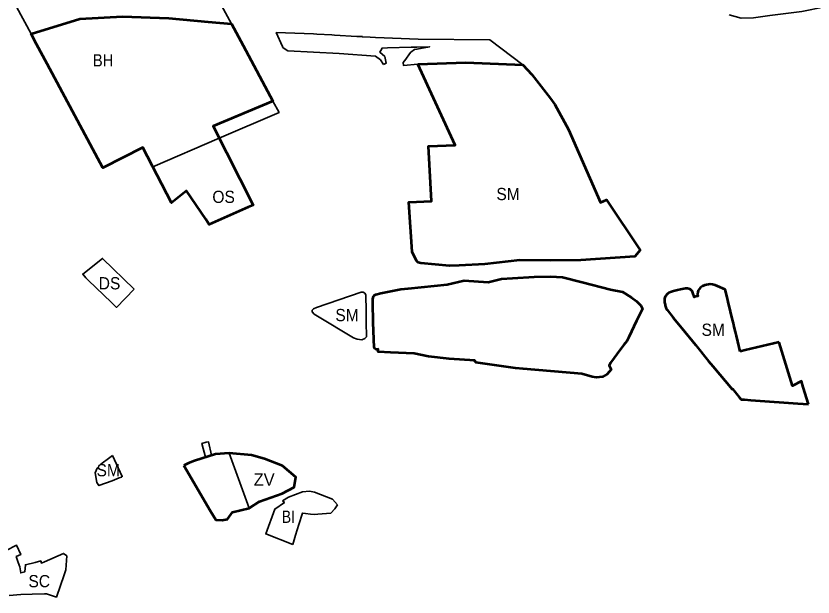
# Model space of a CAD drawing. Extents: x -650276 to -642489, y -1074311 to -1066658.
# Drawn here: x -647428 to -646647, y -1070424 to -1069855 of the extents above; entities that cross this region are included whole.
import ezdxf

# ---------------------------------------------------------------- set-up
doc = ezdxf.new("R2010")
doc.units = 0
doc.header["$LTSCALE"] = 4.8
for name, color, linetype, lineweight in [('1', 7, 'Continuous', 35), ('15', 7, 'Continuous', 35), ('17', 7, 'Continuous', 35), ('18', 7, 'Continuous', 35), ('2', 7, 'Continuous', 35), ('24', 7, 'Continuous', 35), ('25', 7, 'Continuous', 35), ('40', 7, 'Continuous', 35), ('60', 7, 'Continuous', 53), ('9', 7, 'Continuous', 35)]:
    doc.layers.add(name, color=color, linetype=linetype, lineweight=lineweight)
doc.layers.add('62', color=7, linetype='Continuous')
doc.layers.add('63', color=7, linetype='Continuous')

msp = doc.modelspace()

# ---------------------------------------------------------------- linework, layer by layer
at = {"layer": '1'}
msp.add_lwpolyline([(-647365.866, -1069857.774), (-647413.461, -1069872.442), (-647343.28, -1070003.81), (-647339.69, -1070001.95), (-647330.5, -1069997.19), (-647304.05, -1069983.79), (-647294.257, -1070002.745), (-647229.096, -1069974.658), (-647235, -1069963), (-647176.499, -1069938.333), (-647205.781, -1069883.796), (-647217.177, -1069862.57), (-647243.231, -1069860.34), (-647278.525, -1069857.002), (-647323.794, -1069855.468)], close=True, dxfattribs=at)
at = {"layer": '15'}
for points in [[(-647217.177, -1069862.57), (-647228.77, -1069840.98), (-647232.66, -1069841.07), (-647266.62, -1069837.86), (-647270.71, -1069837.61), (-647285.9, -1069836.66), (-647326.71, -1069835.46), (-647363.21, -1069836.64), (-647425.73, -1069844.31), (-647427.62, -1069845.94), (-647413.461, -1069872.442), (-647365.866, -1069857.774), (-647323.794, -1069855.468), (-647278.525, -1069857.002), (-647239.912, -1069860.654)], [(-647235, -1069963), (-647176.499, -1069938.333), (-647170.546, -1069949.42), (-647229.096, -1069974.658)], [(-647242.698, -1070287.238), (-647236.567, -1070285.154), (-647239.781, -1070272.031), (-647242.06, -1070272.35), (-647246.28, -1070273.733)]]:
    msp.add_lwpolyline(points, close=True, dxfattribs=at)
for points in [[(-646931.67, -1069902.89), (-646964.111, -1069878.315), (-647034.195, -1069877.629), (-647076, -1069875.85), (-647081.25, -1069875.56), (-647081.26, -1069875.76), (-647088.94, -1069875.34), (-647088.93, -1069875.14), (-647094.24, -1069874.85), (-647116.31, -1069873.65), (-647118.77, -1069873.51), (-647133.58, -1069872.73), (-647136.94, -1069872.55), (-647173.23, -1069871.09), (-647167.14, -1069884.85)], [(-647167.14, -1069884.85), (-647166.8, -1069885.63), (-647163.55, -1069887.98), (-647162.03, -1069888.89), (-647111.76, -1069891.77)], [(-647111.76, -1069891.77), (-647075.97, -1069894.33), (-647071, -1069897.87), (-647068.2, -1069902.28)], [(-647068.2, -1069902.28), (-647065.47, -1069901.09), (-647067.02, -1069894.68), (-647071.73, -1069890.39), (-647070.87, -1069888.71), (-647069.57, -1069886.35), (-647064.32, -1069886.23), (-647041.25, -1069885.62), (-647035.6, -1069885.43), (-647023.04, -1069885), (-647035.53, -1069887.44), (-647037.79, -1069887.88), (-647041.47, -1069890.42), (-647042.75, -1069892.14), (-647046.49, -1069897.19), (-647048.8, -1069900.51), (-647048.67, -1069903.32), (-647034.51, -1069902.21)], [(-647034.51, -1069902.21), (-647032.16, -1069902.13), (-646987.56, -1069900.52), (-646931.67, -1069902.89)]]:
    msp.add_lwpolyline(points, dxfattribs=at)
at = {"layer": '17'}
msp.add_lwpolyline([(-647434.85, -1070422.64), (-647423.38, -1070421.87), (-647412.51, -1070421.5), (-647400.41, -1070421.08), (-647398.21, -1070421.15), (-647388.6, -1070424.24), (-647381.11, -1070402.45), (-647379.3, -1070397.57), (-647378.49, -1070383.91), (-647381.65, -1070381.45), (-647400.22, -1070389.64), (-647403.27, -1070390.91), (-647404, -1070388.84), (-647409.36, -1070390.24), (-647419.08, -1070392.52), (-647419.68, -1070399.59), (-647423.58, -1070400.59), (-647424.54, -1070394.78), (-647425.99, -1070390.47), (-647427.96, -1070384.64), (-647423.57, -1070382.64), (-647427.8, -1070373.32), (-647437.76, -1070378.66)], dxfattribs=at)
at = {"layer": '18'}
for points in [[(-647032.16, -1069902.13), (-647034.51, -1069902.21), (-646998.06, -1069981.49), (-647024.05, -1069982.48), (-647021.27, -1070036.28), (-647043.25, -1070037.29), (-647040.12, -1070086.11), (-647036.03, -1070094.96), (-647034.17, -1070096.49), (-647031.73, -1070097.21), (-647003.49, -1070099.66), (-646993.92, -1070099.49), (-646968.89, -1070098.02), (-646934.63, -1070094.24), (-646904.97, -1070094.52), (-646874.9, -1070094.1), (-646859.29, -1070093.1), (-646821.89, -1070090.7), (-646817.15, -1070084.76), (-646816.9, -1070084.45), (-646837.65, -1070053.22), (-646849.79, -1070035.17), (-646855.62, -1070037.66), (-646886.85, -1069966.26), (-646900.26, -1069941.64), (-646904.72, -1069935.84), (-646922.79, -1069912.31), (-646931.67, -1069902.89), (-646987.56, -1069900.52)], [(-647097.63, -1070170.37), (-647093.89, -1070171.55), (-647089.47, -1070172.21), (-647086.62, -1070170.89), (-647084.98, -1070169.29), (-647085.17, -1070154.78), (-647085.24, -1070144.07), (-647085.62, -1070128.24), (-647086.49, -1070126.62), (-647088.08, -1070125.63), (-647090.2, -1070125.64), (-647133.96, -1070140.44), (-647136.65, -1070141.75), (-647137.99, -1070143.09), (-647137.96, -1070144.66), (-647136.09, -1070146.97), (-647132.95, -1070149.08)], [(-647333.87, -1070285.66), (-647324.11, -1070306.21), (-647324.94, -1070306.63), (-647327.18, -1070307.52), (-647333.97, -1070310.22), (-647346.97, -1070315.05), (-647349, -1070312), (-647350.67, -1070302.55), (-647348.677, -1070297.894), (-647345.27, -1070293.99), (-647343.9, -1070292.96), (-647337.56, -1070288.43), (-647334.91, -1070286.51)]]:
    msp.add_lwpolyline(points, close=True, dxfattribs=at)
for points in [[(-646748.31, -1070117.83), (-646753.45, -1070118.63), (-646755.74, -1070119.56), (-646757.76, -1070121.07), (-646759.06, -1070122.6), (-646759.78, -1070124), (-646760.32, -1070125.55), (-646760.5, -1070127.58), (-646760.22, -1070129.42), (-646762.07, -1070129.91), (-646763.9, -1070130.41), (-646763.98, -1070130.1), (-646764, -1070129.86), (-646764.94, -1070127.21), (-646765.19, -1070126.23), (-646765.51, -1070125.28), (-646765.97, -1070124.42), (-646767.38, -1070123), (-646768.25, -1070122.53), (-646769.17, -1070122.15), (-646770.43, -1070121.92), (-646772.19, -1070121.98), (-646777.37, -1070122.79), (-646780.28, -1070123.41), (-646784.13, -1070124.41), (-646787, -1070125.38), (-646788.77, -1070126.26), (-646789.61, -1070126.79), (-646791.03, -1070128.23)], [(-646718.8, -1070183.56), (-646721.09, -1070173.94), (-646722.4, -1070168.45), (-646723.4, -1070164.29), (-646724.86, -1070158.17), (-646725.39, -1070155.78), (-646726.17, -1070152.7), (-646728.14, -1070144.51), (-646730.45, -1070134.85), (-646731.54, -1070130.28), (-646733.35, -1070122.79), (-646740.92, -1070119.57), (-646743.33, -1070118.51), (-646745.78, -1070117.96), (-646748.31, -1070117.83)], [(-646791.03, -1070128.23), (-646791.64, -1070129), (-646792.11, -1070129.89), (-646792.76, -1070131.79), (-646792.97, -1070133.76), (-646792.84, -1070135.73), (-646792.42, -1070137.71), (-646792.18, -1070138.48), (-646791.84, -1070139.56), (-646791.13, -1070141.44), (-646790.86, -1070142.02), (-646790.29, -1070142.85), (-646784.8, -1070149.86), (-646784.45, -1070150.291)], [(-646784.45, -1070150.291), (-646784.18, -1070150.61), (-646783.937, -1070150.923), (-646775.93, -1070160.78), (-646762.52, -1070177.24)], [(-646762.52, -1070177.24), (-646749.79, -1070193.02), (-646745.61, -1070198.15), (-646726.48, -1070220.46), (-646726.36, -1070220.34), (-646719.7, -1070228.25), (-646717.71, -1070230.56)], [(-646680.68, -1070174.5), (-646713.74, -1070182.36), (-646718.8, -1070183.56)], [(-646651.86, -1070235.22), (-646656.96, -1070218.43), (-646658.64, -1070212.77), (-646667.64, -1070217.36), (-646680.61, -1070174.79), (-646680.68, -1070174.5)], [(-646717.71, -1070230.56), (-646714.42, -1070230.81), (-646708.2, -1070231.25), (-646703.67, -1070231.58), (-646662.41, -1070234.57), (-646651.86, -1070235.22)]]:
    msp.add_lwpolyline(points, dxfattribs=at)
at = {"layer": '2'}
for points in [[(-647113.37, -1070333.96), (-647118.28, -1070328.29), (-647135.94, -1070321.54), (-647140.83, -1070320.47), (-647147.66, -1070321.04), (-647161.17, -1070326.29), (-647167.03, -1070329.81)], [(-647167.03, -1070329.81), (-647165.36, -1070331.59), (-647174.81, -1070338.01), (-647183.55, -1070362.35), (-647156.9, -1070372.69)], [(-647132.49, -1070342.91), (-647119.88, -1070342.1), (-647116.03, -1070337.68), (-647113.37, -1070333.96)], [(-647156.9, -1070372.69), (-647154.31, -1070363.46), (-647151.09, -1070353.15), (-647147.6, -1070341.95), (-647144.57, -1070342.42), (-647139.84, -1070343.16), (-647135.62, -1070343.32), (-647132.49, -1070342.91)]]:
    msp.add_lwpolyline(points, dxfattribs=at)
at = {"layer": '24'}
msp.add_lwpolyline([(-647312.485, -1070122.583), (-647329.932, -1070140.465), (-647334.81, -1070135.73), (-647357.4, -1070113.69), (-647359.8, -1070111.34), (-647362.87, -1070107.74), (-647343.454, -1070092.368)], close=True, dxfattribs=at)
at = {"layer": '25'}
msp.add_lwpolyline([(-646515.63, -1069810.24), (-646522.32, -1069812.28), (-646560.92, -1069825.33), (-646613.65, -1069840.02), (-646620.06, -1069841.69), (-646629.83, -1069844.23), (-646635.93, -1069845.82), (-646658.5, -1069850.59), (-646689.73, -1069854.58), (-646705.87, -1069856.62), (-646717.66, -1069857.11), (-646729.54, -1069853.69)], dxfattribs=at)
at = {"layer": '40'}
msp.add_lwpolyline([(-647199.79, -1070337.21), (-647189.63, -1070330.53), (-647167.43, -1070322.66), (-647155.89, -1070316.51), (-647154.23, -1070306.63), (-647167.15, -1070295.69), (-647184.77, -1070288.73), (-647197.68, -1070285.3), (-647219.36, -1070283.36)], close=True, dxfattribs=at)
at = {"layer": '60'}
for points in [[(-647408.115, -1069882.449), (-647413.461, -1069872.442), (-647365.866, -1069857.774), (-647323.794, -1069855.468), (-647278.525, -1069857.002), (-647239.912, -1069860.654), (-647217.177, -1069862.57), (-647205.781, -1069883.796), (-647176.499, -1069938.333), (-647235, -1069963), (-647195.933, -1070040.107), (-647200.796, -1070042.246), (-647238.99, -1070059.05), (-647238.99, -1070059.05), (-647242.362, -1070054.067), (-647261.27, -1070026.12), (-647276, -1070038.08), (-647304.05, -1069983.79), (-647343.28, -1070003.81), (-647397.738, -1069901.873)], [(-647034.51, -1069902.21), (-646987.56, -1069900.52), (-646931.67, -1069902.89), (-646922.79, -1069912.31), (-646904.72, -1069935.84), (-646900.26, -1069941.64), (-646886.85, -1069966.26), (-646855.62, -1070037.66), (-646849.79, -1070035.17), (-646816.9, -1070084.45), (-646821.89, -1070090.7), (-646874.9, -1070094.1), (-646904.97, -1070094.52), (-646934.63, -1070094.24), (-646968.89, -1070098.02), (-646993.92, -1070099.49), (-647003.49, -1070099.66), (-647031.73, -1070097.21), (-647034.17, -1070096.49), (-647036.03, -1070094.96), (-647040.12, -1070086.11), (-647043.25, -1070037.29), (-647021.27, -1070036.28), (-647024.05, -1069982.48), (-646998.06, -1069981.49)], [(-647076.99, -1070128.48), (-647075.81, -1070127.72), (-647070.7, -1070126.64), (-647051.14, -1070122.49), (-647044.19, -1070121.78), (-647005.97, -1070117.89), (-646989.24, -1070114.17), (-646989.24, -1070114.17), (-646965.6, -1070115.74), (-646952.66, -1070112.57), (-646941.99, -1070111.74), (-646920.68, -1070110.58), (-646904.66, -1070110.24), (-646892.87, -1070110.82), (-646873.5, -1070115.8), (-646845.78, -1070122.84), (-646834.04, -1070125.34), (-646825.4, -1070130.78), (-646820.35, -1070134.43), (-646816.06, -1070138.5), (-646814.53, -1070141.96), (-646820.51, -1070153.68), (-646827.95, -1070169.52), (-646829.87, -1070173.61), (-646832.62, -1070177.08), (-646836.06, -1070181.31), (-646845.76, -1070194.67), (-646847.17, -1070197.38), (-646845.3, -1070201.3), (-646849.15, -1070205.9), (-646853.67, -1070208.44), (-646859.54, -1070209.09), (-646863.66, -1070208.37), (-646874.04, -1070205.5), (-646931.25, -1070200.56), (-646938.98, -1070199.89), (-646977.7, -1070194.45), (-646977.7, -1070193.62), (-646978.72, -1070193.6), (-646978.73, -1070192.54), (-647003.89, -1070190.89), (-647024.2, -1070188.68), (-647038.31, -1070185.73), (-647061.2, -1070184.6), (-647073.35, -1070184.01), (-647073.42, -1070181.47), (-647075.42, -1070181.53), (-647076.83, -1070180.73), (-647077.39, -1070179.57), (-647078.23, -1070155.29), (-647078.72, -1070135.49), (-647078.54, -1070132.1), (-647078.05, -1070129.8)], [(-647263.72, -1070295.43), (-647237.57, -1070340.12), (-647232.55, -1070348.65), (-647226.24, -1070348.88), (-647220.9, -1070348.04), (-647216.16, -1070340.99), (-647199.79, -1070337.21), (-647189.63, -1070330.53), (-647167.43, -1070322.66), (-647155.89, -1070316.51), (-647154.23, -1070306.63), (-647167.15, -1070295.69), (-647184.77, -1070288.73), (-647197.68, -1070285.3), (-647219.36, -1070283.36), (-647232.87, -1070284.15), (-647253.53, -1070290.92), (-647259.22, -1070292.91)]]:
    msp.add_lwpolyline(points, close=True, dxfattribs=at)
for points in [[(-646748.31, -1070117.83), (-646753.45, -1070118.63), (-646755.74, -1070119.56), (-646757.76, -1070121.07), (-646759.06, -1070122.6), (-646759.78, -1070124), (-646760.32, -1070125.55), (-646760.5, -1070127.58), (-646760.22, -1070129.42), (-646762.07, -1070129.91), (-646763.9, -1070130.41), (-646763.98, -1070130.1), (-646764, -1070129.86), (-646764.94, -1070127.21), (-646765.19, -1070126.23), (-646765.51, -1070125.28), (-646765.97, -1070124.42), (-646767.38, -1070123), (-646768.25, -1070122.53), (-646769.17, -1070122.15), (-646770.43, -1070121.92), (-646772.19, -1070121.98), (-646777.37, -1070122.79), (-646780.28, -1070123.41), (-646784.13, -1070124.41), (-646787, -1070125.38), (-646788.77, -1070126.26), (-646789.61, -1070126.79), (-646791.03, -1070128.23)], [(-646748.31, -1070117.83), (-646753.45, -1070118.63), (-646755.74, -1070119.56), (-646757.76, -1070121.07), (-646759.06, -1070122.6), (-646759.78, -1070124), (-646760.32, -1070125.55), (-646760.5, -1070127.58), (-646760.22, -1070129.42), (-646762.07, -1070129.91), (-646763.9, -1070130.41), (-646763.98, -1070130.1), (-646764, -1070129.86), (-646764.94, -1070127.21), (-646765.19, -1070126.23), (-646765.51, -1070125.28), (-646765.97, -1070124.42), (-646767.38, -1070123), (-646768.25, -1070122.53), (-646769.17, -1070122.15), (-646770.43, -1070121.92), (-646772.19, -1070121.98), (-646777.37, -1070122.79), (-646780.28, -1070123.41), (-646784.13, -1070124.41), (-646787, -1070125.38), (-646788.77, -1070126.26), (-646789.61, -1070126.79), (-646791.03, -1070128.23)], [(-646718.8, -1070183.56), (-646721.09, -1070173.94), (-646722.4, -1070168.45), (-646723.4, -1070164.29), (-646724.86, -1070158.17), (-646725.39, -1070155.78), (-646726.17, -1070152.7), (-646728.14, -1070144.51), (-646730.45, -1070134.85), (-646731.54, -1070130.28), (-646733.35, -1070122.79), (-646740.92, -1070119.57), (-646743.33, -1070118.51), (-646745.78, -1070117.96), (-646748.31, -1070117.83)], [(-646718.8, -1070183.56), (-646721.09, -1070173.94), (-646722.4, -1070168.45), (-646723.4, -1070164.29), (-646724.86, -1070158.17), (-646725.39, -1070155.78), (-646726.17, -1070152.7), (-646728.14, -1070144.51), (-646730.45, -1070134.85), (-646731.54, -1070130.28), (-646733.35, -1070122.79), (-646740.92, -1070119.57), (-646743.33, -1070118.51), (-646745.78, -1070117.96), (-646748.31, -1070117.83)], [(-646791.03, -1070128.23), (-646791.64, -1070129), (-646792.11, -1070129.89), (-646792.76, -1070131.79), (-646792.97, -1070133.76), (-646792.84, -1070135.73), (-646792.42, -1070137.71), (-646792.18, -1070138.48), (-646791.84, -1070139.56), (-646791.13, -1070141.44), (-646790.86, -1070142.02), (-646790.29, -1070142.85), (-646784.8, -1070149.86), (-646784.45, -1070150.291)], [(-646791.03, -1070128.23), (-646791.64, -1070129), (-646792.11, -1070129.89), (-646792.76, -1070131.79), (-646792.97, -1070133.76), (-646792.84, -1070135.73), (-646792.42, -1070137.71), (-646792.18, -1070138.48), (-646791.84, -1070139.56), (-646791.13, -1070141.44), (-646790.86, -1070142.02), (-646790.29, -1070142.85), (-646784.8, -1070149.86), (-646784.45, -1070150.291)], [(-646784.45, -1070150.291), (-646784.18, -1070150.61), (-646783.937, -1070150.923), (-646775.93, -1070160.78), (-646762.52, -1070177.24)], [(-646784.45, -1070150.291), (-646784.18, -1070150.61), (-646783.937, -1070150.923), (-646775.93, -1070160.78), (-646762.52, -1070177.24)], [(-646762.52, -1070177.24), (-646749.79, -1070193.02), (-646745.61, -1070198.15), (-646726.48, -1070220.46), (-646726.36, -1070220.34), (-646719.7, -1070228.25), (-646717.71, -1070230.56)], [(-646762.52, -1070177.24), (-646749.79, -1070193.02), (-646745.61, -1070198.15), (-646726.48, -1070220.46), (-646726.36, -1070220.34), (-646719.7, -1070228.25), (-646717.71, -1070230.56)], [(-646680.68, -1070174.5), (-646713.74, -1070182.36), (-646718.8, -1070183.56)], [(-646680.68, -1070174.5), (-646713.74, -1070182.36), (-646718.8, -1070183.56)], [(-646651.86, -1070235.22), (-646656.96, -1070218.43), (-646658.64, -1070212.77), (-646667.64, -1070217.36), (-646680.61, -1070174.79), (-646680.68, -1070174.5)], [(-646651.86, -1070235.22), (-646656.96, -1070218.43), (-646658.64, -1070212.77), (-646667.64, -1070217.36), (-646680.61, -1070174.79), (-646680.68, -1070174.5)], [(-646717.71, -1070230.56), (-646714.42, -1070230.81), (-646708.2, -1070231.25), (-646703.67, -1070231.58), (-646662.41, -1070234.57), (-646651.86, -1070235.22)], [(-646717.71, -1070230.56), (-646714.42, -1070230.81), (-646708.2, -1070231.25), (-646703.67, -1070231.58), (-646662.41, -1070234.57), (-646651.86, -1070235.22)]]:
    msp.add_lwpolyline(points, dxfattribs=at)
at = {"layer": '9'}
msp.add_lwpolyline([(-647261.27, -1070026.12), (-647238.99, -1070059.05), (-647195.933, -1070040.107), (-647229.096, -1069974.658), (-647294.257, -1070002.745), (-647276, -1070038.08)], close=True, dxfattribs=at)

# ---------------------------------------------------------------- texts
at = {"layer": '62'}
for s, width, p in [('BH', 0.9, (-647352.947, -1069904.358)), ('SM', 0.95, (-646957.615, -1070035.352)), ('OS', 0.95, (-647235.865, -1070038.102)), ('DS', 0.95, (-647347.216, -1070122.778)), ('SM', 0.95, (-647115.357, -1070153.941)), ('SM', 0.95, (-647349.357, -1070305.941)), ('BI', 0.85, (-647167.828, -1070351.569)), ('SC', 0.95, (-647416.06, -1070414.645))]:
    msp.add_text(s, height=12, dxfattribs=dict(at, width=width)).set_placement(p)
msp.add_text('ZV', height=12, dxfattribs=at).set_placement((-647195.386, -1070315.148))
at = {"layer": '63', "width": 0.95}
msp.add_text('SM', height=12, dxfattribs=at).set_placement((-646756.615, -1070168.352))

doc.saveas('drawing.dxf')
